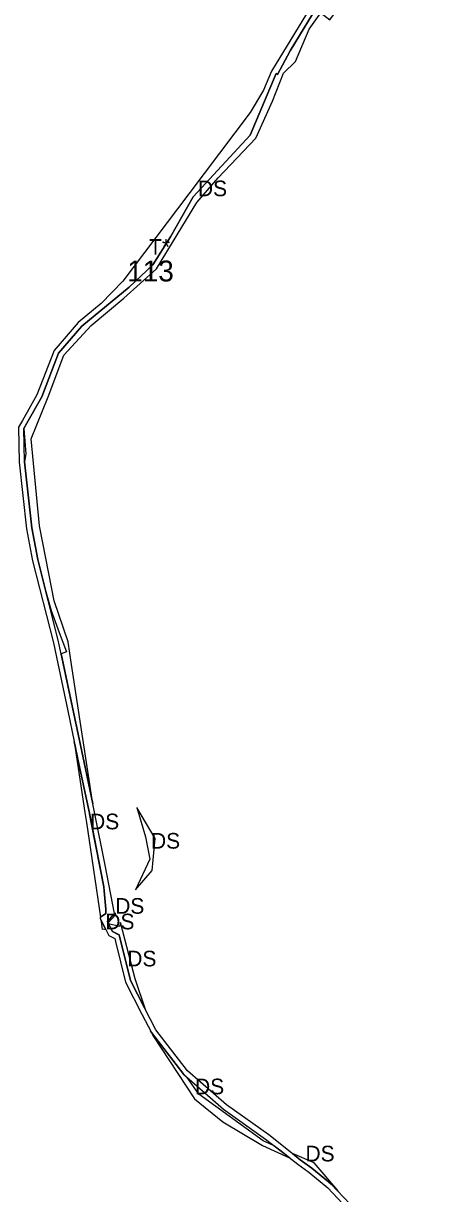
# Model space of a CAD drawing. Extents: x -477304 to -465641, y -1159113 to -1149285.
# Drawn here: x -473380 to -473143, y -1152947 to -1152275 of the extents above; entities that cross this region are included whole.
import ezdxf

# ---------------------------------------------------------------- set-up
doc = ezdxf.new("R2010")
doc.units = 0
for name, color, linetype in [('35', 7, 'Continuous'), ('4', 7, 'Continuous'), ('60', 7, 'Continuous')]:
    doc.layers.add(name, color=color, linetype=linetype)

msp = doc.modelspace()

# ---------------------------------------------------------------- linework, layer by layer
at = {"layer": '35'}
for p, q in [((-473208.69, -1152260.28), (-473226.7, -1152290.37)), ((-473226.7, -1152290.37), (-473234.12, -1152303.84)), ((-473280.32, -1152377.43), (-473268.17, -1152363.31)), ((-473295.54, -1152397.17), (-473305.65, -1152413.28)), ((-473359.75, -1152464.05), (-473369.42, -1152489.14)), ((-473379.28, -1152526.37), (-473375.13, -1152564.43)), ((-473375.13, -1152564.43), (-473371.72, -1152582.63)), ((-473371.72, -1152582.63), (-473367.43, -1152599.57)), ((-473362.2, -1152606.24), (-473365.42, -1152590.64)), ((-473367.43, -1152599.57), (-473363.92, -1152611.91)), ((-473354.3, -1152629.93), (-473362.2, -1152606.24)), ((-473363.92, -1152611.91), (-473359.43, -1152624.58)), ((-473359.43, -1152624.58), (-473355.16, -1152635.57)), ((-473352.33, -1152642.86), (-473354.3, -1152629.93)), ((-473355.16, -1152635.57), (-473358.34, -1152636.65)), ((-473358.34, -1152636.65), (-473345.12, -1152699.23)), ((-473340.13, -1152722.95), (-473352.33, -1152642.86)), ((-473350.75, -1152687.1), (-473344.66, -1152727.89)), ((-473345.12, -1152699.23), (-473340.13, -1152722.95)), ((-473344.66, -1152727.89), (-473343.79, -1152733.72)), ((-473343.79, -1152733.72), (-473335.68, -1152788.04)), ((-473342, -1152728.62), (-473342.08, -1152728.26)), ((-473340.83, -1152734.56), (-473342, -1152728.62)), ((-473333.67, -1152770.63), (-473340.83, -1152734.56)), ((-473307.35, -1152754.74), (-473315.65, -1152772.24)), ((-473329.13, -1152789.02), (-473326.96, -1152786.45)), ((-473327.08, -1152785.71), (-473327.56, -1152786.04)), ((-473326.96, -1152786.45), (-473327.08, -1152785.71)), ((-473334.6, -1152791.28), (-473335.45, -1152789.57)), ((-473335.45, -1152789.57), (-473335.09, -1152791.98)), ((-473335.09, -1152791.98), (-473334.86, -1152793.51)), ((-473334.86, -1152793.51), (-473334.63, -1152795.03)), ((-473334.63, -1152795.03), (-473334.37, -1152794.74)), ((-473334.14, -1152792.21), (-473334.6, -1152791.28)), ((-473334.37, -1152794.74), (-473332.67, -1152795.19)), ((-473333.41, -1152793.69), (-473334.14, -1152792.21)), ((-473332.67, -1152795.19), (-473333.41, -1152793.69)), ((-473331.59, -1152790.6), (-473331.23, -1152791.32)), ((-473331.23, -1152791.32), (-473329.13, -1152789.02)), ((-473324.79, -1152793.4), (-473330.99, -1152791.81)), ((-473324.18, -1152791.02), (-473324.79, -1152793.4)), ((-473315.8, -1152823.53), (-473324.18, -1152791.02)), ((-473328.74, -1152796.35), (-473325.89, -1152797.71)), ((-473325.89, -1152797.71), (-473325.65, -1152797.82)), ((-473325.65, -1152797.82), (-473325.59, -1152797.85)), ((-473309.6, -1152841.64), (-473315.8, -1152823.53)), ((-473310.35, -1152840.19), (-473309.6, -1152841.64)), ((-473287.86, -1152878.34), (-473292.31, -1152872.59)), ((-473285.9, -1152880.06), (-473287.86, -1152878.34)), ((-473279.3, -1152889.81), (-473285.9, -1152880.06)), ((-473281.74, -1152892.46), (-473265.48, -1152905.6)), ((-473242.38, -1152916.54), (-473279.3, -1152889.81)), ((-473265.48, -1152905.6), (-473242.63, -1152919.25)), ((-473242.63, -1152919.25), (-473227.2, -1152926.29)), ((-473236.3, -1152919.16), (-473242.38, -1152916.54)), ((-473212.99, -1152929.2), (-473225.52, -1152923.8)), ((-473225.52, -1152923.8), (-473220.96, -1152927.38)), ((-473199.49, -1152945.03), (-473212.99, -1152929.2)), ((-473204.72, -1152940.11), (-473203.16, -1152941.34)), ((-473203.16, -1152941.34), (-473199.3, -1152945.48)), ((-473199.3, -1152945.48), (-473199.49, -1152945.03))]:
    msp.add_line(p, q, dxfattribs=at)
for points in [[(-473236.85, -1152319.14), (-473230.55, -1152303.09), (-473223.74, -1152296.46), (-473215.82, -1152277.94), (-473209.15, -1152268.48), (-473203.92, -1152272.59), (-473183.44, -1152244.15), (-473185.05, -1152242.6)], [(-473234.12, -1152303.84), (-473234.77, -1152303.3), (-473249.72, -1152338.71), (-473282.57, -1152374.28), (-473295.54, -1152397.17)], [(-473268.17, -1152363.31), (-473246.56, -1152340.4), (-473236.85, -1152319.14)], [(-473341.01, -1152448.06), (-473322.37, -1152432.38), (-473303.45, -1152415.46), (-473280.32, -1152377.43)], [(-473305.65, -1152413.28), (-473319.19, -1152426.04), (-473346.36, -1152448.57), (-473359.75, -1152464.05)], [(-473375.41, -1152513.2), (-473365.75, -1152489.08), (-473356.77, -1152465.14), (-473341.01, -1152448.06)], [(-473369.42, -1152489.14), (-473377.92, -1152504.24), (-473379.75, -1152507.27)], [(-473379.75, -1152507.27), (-473378.45, -1152521.81), (-473379.28, -1152526.37)], [(-473365.42, -1152590.64), (-473370.71, -1152563.16), (-473375.41, -1152513.2)], [(-473342.08, -1152728.26), (-473348.06, -1152699.85), (-473350.75, -1152687.1)], [(-473304.28, -1152742.75), (-473314.8, -1152725.09), (-473309.75, -1152741.94), (-473307.35, -1152754.74)], [(-473315.65, -1152772.24), (-473306.07, -1152761.24), (-473304.28, -1152742.75)], [(-473332.66, -1152783.53), (-473333.49, -1152772.95), (-473333.67, -1152770.63)], [(-473335.68, -1152788.04), (-473332.56, -1152785.87), (-473332.66, -1152783.53)], [(-473327.56, -1152786.04), (-473327.98, -1152786.33), (-473331.59, -1152790.6)], [(-473330.99, -1152791.81), (-473328.82, -1152796.19), (-473328.74, -1152796.35)], [(-473325.59, -1152797.85), (-473325.32, -1152797.98), (-473324.91, -1152798.17), (-473318.52, -1152824.36), (-473310.35, -1152840.19)], [(-473292.31, -1152872.59), (-473306.4, -1152854.38), (-473306.94, -1152853.33)], [(-473306.94, -1152853.33), (-473305.72, -1152856.02), (-473281.74, -1152892.46)], [(-473227.2, -1152926.29), (-473232.03, -1152922.51), (-473236.3, -1152919.16)], [(-473220.96, -1152927.38), (-473214.29, -1152932.19), (-473204.72, -1152940.11)]]:
    msp.add_lwpolyline(points, dxfattribs=at)
at = {"layer": '4'}
for p, q in [((-473226.7, -1152290.37), (-473208.69, -1152260.28)), ((-473234.12, -1152303.84), (-473226.7, -1152290.37)), ((-473234.77, -1152303.3), (-473234.12, -1152303.84)), ((-473242.08, -1152312.91), (-473249.76, -1152325.8)), ((-473345.12, -1152699.23), (-473359.83, -1152629.63)), ((-473354.47, -1152669.52), (-473350.75, -1152687.1)), ((-473340.13, -1152722.95), (-473345.12, -1152699.23)), ((-473342.08, -1152728.26), (-473333.67, -1152770.63)), ((-473335.45, -1152789.57), (-473332.67, -1152795.19)), ((-473325.65, -1152797.82), (-473328.74, -1152796.35)), ((-473327.48, -1152800.27), (-473327.06, -1152802.01)), ((-473292.31, -1152872.59), (-473287.86, -1152878.34)), ((-473287.86, -1152878.34), (-473265.11, -1152898.31)), ((-473265.11, -1152898.31), (-473240.88, -1152915.57)), ((-473203.16, -1152941.34), (-473204.72, -1152940.11)), ((-473202.53, -1152946.42), (-473196.6, -1152952.79))]:
    msp.add_line(p, q, dxfattribs=at)
for points in [[(-473142.73, -1152168.39), (-473158.4, -1152190.96), (-473190.78, -1152234.32), (-473211.14, -1152258.53), (-473237.45, -1152301.93), (-473242.08, -1152312.91)], [(-473359.83, -1152629.63), (-473371.72, -1152582.63), (-473375.13, -1152564.43), (-473379.28, -1152526.37), (-473379.75, -1152507.27), (-473377.92, -1152504.24), (-473369.42, -1152489.14), (-473359.75, -1152464.05), (-473346.36, -1152448.57), (-473319.19, -1152426.04), (-473305.65, -1152413.28), (-473295.54, -1152397.17), (-473282.57, -1152374.28), (-473249.72, -1152338.71), (-473234.77, -1152303.3)], [(-473249.76, -1152325.8), (-473285.01, -1152372.5), (-473322.9, -1152422.7), (-473335.26, -1152435.47)], [(-473335.26, -1152435.47), (-473348.47, -1152446.42), (-473362.36, -1152462.48), (-473372.14, -1152487.86), (-473380.51, -1152502.73), (-473382.77, -1152506.47), (-473382.28, -1152526.57), (-473378.1, -1152564.87), (-473374.65, -1152583.27), (-473362.74, -1152630.36)], [(-473362.74, -1152630.36), (-473360.97, -1152638.74), (-473354.47, -1152669.52)], [(-473350.75, -1152687.1), (-473348.06, -1152699.85), (-473342.08, -1152728.26)], [(-473331.59, -1152790.6), (-473327.98, -1152786.33), (-473327.56, -1152786.04), (-473327.59, -1152785.88), (-473333.09, -1152758.17), (-473339.14, -1152727.66), (-473340.13, -1152722.95)], [(-473333.67, -1152770.63), (-473333.49, -1152772.95), (-473332.66, -1152783.53)], [(-473332.66, -1152783.53), (-473332.56, -1152785.87), (-473335.68, -1152788.04), (-473336.07, -1152788.31), (-473335.94, -1152788.57), (-473335.45, -1152789.57)], [(-473332.67, -1152795.19), (-473330.97, -1152798.62), (-473327.48, -1152800.27)], [(-473328.74, -1152796.35), (-473328.82, -1152796.19), (-473330.99, -1152791.81), (-473331.59, -1152790.6)], [(-473327.06, -1152802.01), (-473321.34, -1152825.42), (-473311.86, -1152843.81)], [(-473310.35, -1152840.19), (-473318.52, -1152824.36), (-473324.91, -1152798.17), (-473325.32, -1152797.98), (-473325.65, -1152797.82)], [(-473285.67, -1152876.27), (-473303.86, -1152852.76), (-473310.35, -1152840.19)], [(-473311.86, -1152843.81), (-473306.4, -1152854.38), (-473292.31, -1152872.59)], [(-473220.96, -1152927.38), (-473239.09, -1152913.16), (-473263.25, -1152895.95), (-473285.67, -1152876.27)], [(-473240.88, -1152915.57), (-473232.03, -1152922.51), (-473222.48, -1152929.99), (-473216.14, -1152934.55), (-473205.19, -1152943.55), (-473202.53, -1152946.42)], [(-473204.72, -1152940.11), (-473214.29, -1152932.19), (-473220.96, -1152927.38)], [(-473160.62, -1152993.52), (-473175.02, -1152971.59), (-473192.31, -1152952.99), (-473203.16, -1152941.34)]]:
    msp.add_lwpolyline(points, dxfattribs=at)

# ---------------------------------------------------------------- texts
at = {"layer": '35'}
for p in [(-473279.71, -1152373.86), (-473341.66, -1152737.57), (-473306.67, -1152748.67), (-473327.22, -1152786.07), (-473332.89, -1152795.05), (-473320.29, -1152816.33), (-473281.39, -1152889.81), (-473217.99, -1152928.36)]:
    msp.add_text('DS', height=9, dxfattribs=at).set_placement(p)
at = {"layer": '4'}
msp.add_text('T*', height=9, dxfattribs=at).set_placement((-473307.76, -1152407.49))
at = {"layer": '60'}
msp.add_text('113', height=12, dxfattribs=at).set_placement((-473320.36, -1152422.8))

doc.saveas('drawing.dxf')
